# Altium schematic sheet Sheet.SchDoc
size A4
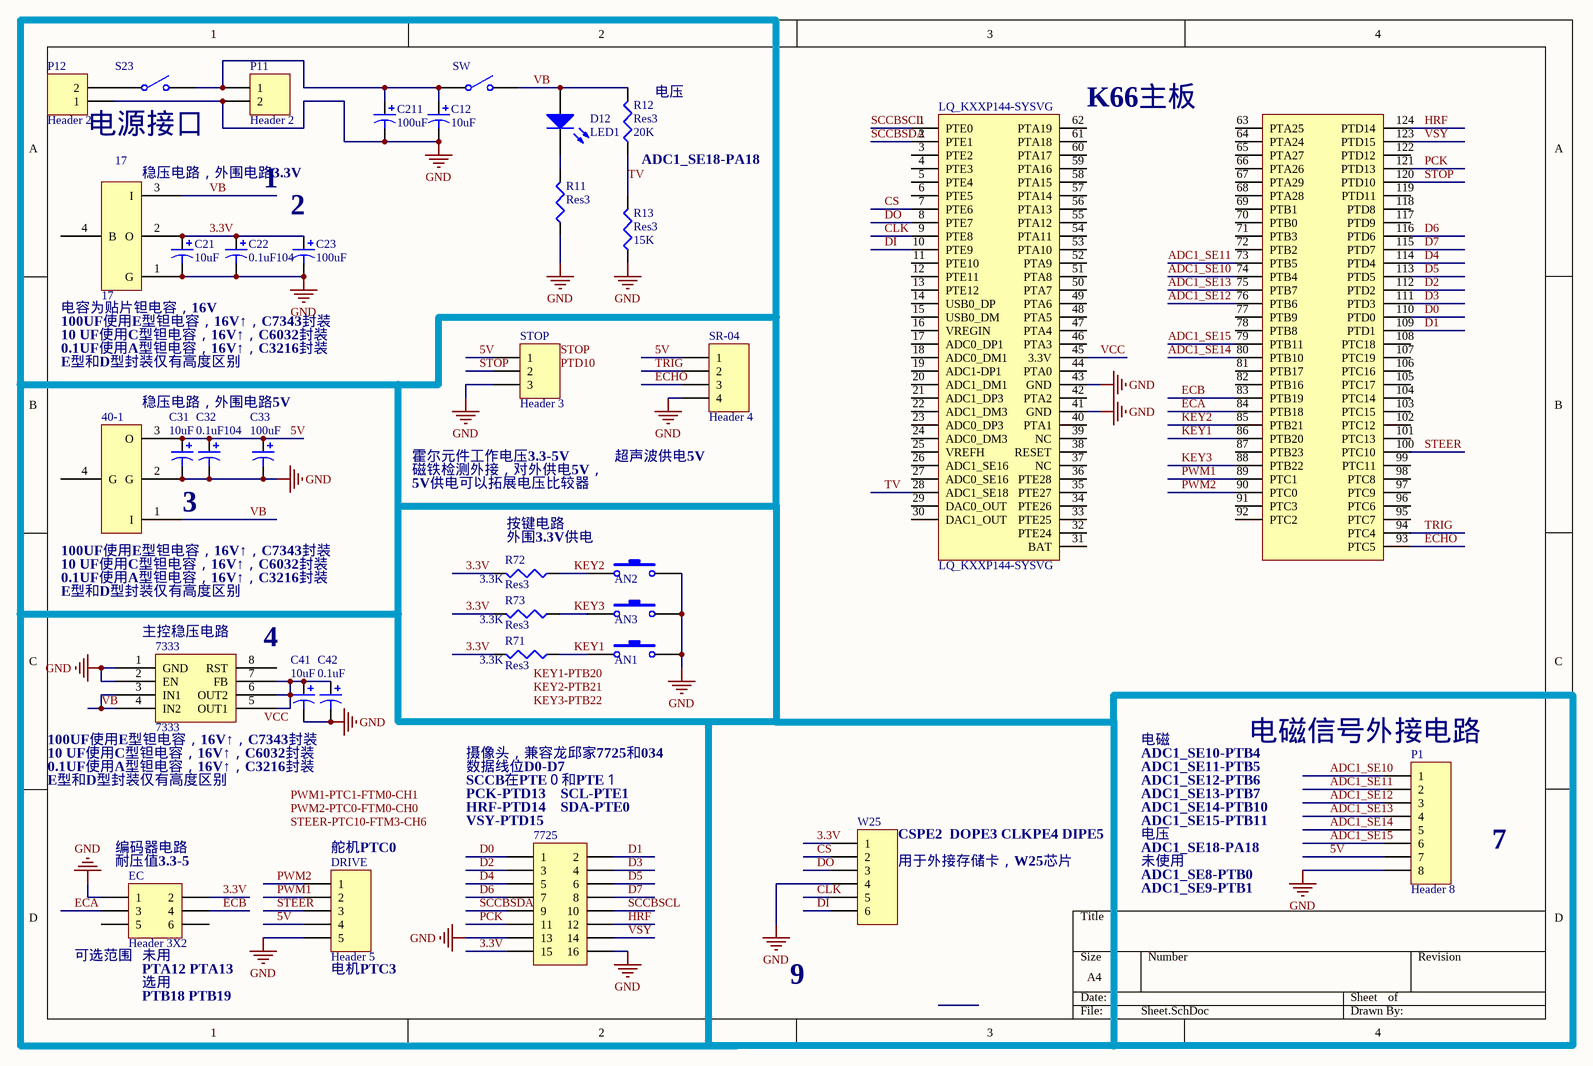
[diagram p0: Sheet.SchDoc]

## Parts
17  17  [SOT-223]
40-1  40-1  [TO-220B]  (value not drawn)
7333  7333  [SO8_N]
7725  Header 8X2  [HDR2X8]  (value not drawn)
AN1  Button  [SMT4*6*2.5]  (value not drawn)
AN2  Button  [SMT4*6*2.5]  (value not drawn)
AN3  Button  [SMT4*6*2.5]  (value not drawn)
C12  value 10uF  [C6032]  (hidden comment: Cap Pol3)
C21  value 10uF  [C6032]  (hidden comment: Cap Pol3)
C22  value 0.1uF104  [C3216]  (hidden comment: Cap Pol3)
C23  value 100uF  [C7343]  (hidden comment: Cap Pol3)
C31  value 10uF  [C6032]  (hidden comment: Cap Pol3)
C32  value 0.1uF104  [C3216]  (hidden comment: Cap Pol3)
C33  value 100uF  [C7343]  (hidden comment: Cap Pol3)
C41  value 10uF  [C6032]  (hidden comment: Cap Pol3)
C42  value 0.1uF  [C3216]  (hidden comment: Cap Pol3)
C211  value 100uF  [C7343]  (hidden comment: Cap Pol3)
D12  LED1  [SMA]
DRIVE  Header 5  [HDR1X5]
EC  Header 3X2  [HDR2X3]
LQ_KXXP144-SYSVG  LQ_KXXP144-SYSVG  [LQ_KXXP144-SYSVG]
P1  Header 8  [HDR1X8]
P11  Header 2  [T_Plug]
P12  Header 2  [2PIN-5.08A]
R11  Res3  [R0805]
R12  Res3  value 20K  [R0805]
R13  Res3  value 15K  [R0805]
R71  Res3  value 3.3K  [R0805]
R72  Res3  value 3.3K  [R0805]
R73  Res3  value 3.3K  [R0805]
S1  SW  [MTS-103]
S23  S2W  [MTS-103]  (value not drawn)
SR-04  Header 4  [HDR1X4]
STOP  Header 3  [HDR1X3]
W25  MHDR1X6  [HDR1X6]  (value not drawn)

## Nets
GND: 17.1(G) 40-1.2(G) 7333.1(GND) 7333.2(EN) 7725.13 7725.16 AN1.1 AN2.1 AN3.1 C12.2 C21.2 C22.2 C23.2 C31.2 C32.2 C33.2 C41.2 C42.2 C211.2 DRIVE.5 EC.1 LQ_KXXP144-SYSVG.41(GND) LQ_KXXP144-SYSVG.43(GND) P1.8 P11.2 P12.1 R11.1 R13.1 SR-04.4 STOP.3 W25.4
3.3V: 17.2(O) 7725.15 C21.1 C22.1 C23.1 EC.2 R71.2 R72.2 R73.2 W25.1
5V: 40-1.3(O) C31.1 C32.1 C33.1 DRIVE.4 P1.7 SR-04.1 STOP.1
ADC1_SE10: LQ_KXXP144-SYSVG.74(PTB4) P1.1
ADC1_SE11: LQ_KXXP144-SYSVG.73(PTB5) P1.2
ADC1_SE12: LQ_KXXP144-SYSVG.76(PTB6) P1.3
ADC1_SE13: LQ_KXXP144-SYSVG.75(PTB7) P1.4
ADC1_SE14: LQ_KXXP144-SYSVG.80(PTB10) P1.5
ADC1_SE15: LQ_KXXP144-SYSVG.79(PTB11) P1.6
CLK: LQ_KXXP144-SYSVG.9(PTE8) W25.5
CS: LQ_KXXP144-SYSVG.7(PTE6) W25.2
D0: 7725.1 LQ_KXXP144-SYSVG.110(PTD0)
D1: 7725.2 LQ_KXXP144-SYSVG.109(PTD1)
D2: 7725.3 LQ_KXXP144-SYSVG.112(PTD2)
D3: 7725.4 LQ_KXXP144-SYSVG.111(PTD3)
D4: 7725.5 LQ_KXXP144-SYSVG.114(PTD4)
D5: 7725.6 LQ_KXXP144-SYSVG.113(PTD5)
D6: 7725.7 LQ_KXXP144-SYSVG.116(PTD6)
D7: 7725.8 LQ_KXXP144-SYSVG.115(PTD7)
DI: LQ_KXXP144-SYSVG.10(PTE9) W25.6
DO: LQ_KXXP144-SYSVG.8(PTE7) W25.3
ECA: EC.3 LQ_KXXP144-SYSVG.84(PTB18)
ECB: EC.4 LQ_KXXP144-SYSVG.83(PTB19)
ECHO: LQ_KXXP144-SYSVG.93(PTC5) SR-04.3
HRF: 7725.12 LQ_KXXP144-SYSVG.124(PTD14)
KEY1: AN1.2 LQ_KXXP144-SYSVG.86(PTB20) R71.1
KEY2: AN2.2 LQ_KXXP144-SYSVG.85(PTB21) R72.1
KEY3: AN3.2 LQ_KXXP144-SYSVG.88(PTB22) R73.1
PCK: 7725.11 LQ_KXXP144-SYSVG.121(PTD13)
PWM1: DRIVE.2 LQ_KXXP144-SYSVG.89(PTC1)
PWM2: DRIVE.1 LQ_KXXP144-SYSVG.90(PTC0)
SCCBSCL: 7725.10 LQ_KXXP144-SYSVG.1(PTE0)
SCCBSDA: 7725.9 LQ_KXXP144-SYSVG.2(PTE1)
STEER: DRIVE.3 LQ_KXXP144-SYSVG.100(PTC10)
STOP: LQ_KXXP144-SYSVG.120(PTD10) STOP.2
TRIG: LQ_KXXP144-SYSVG.94(PTC4) SR-04.2
TV: LQ_KXXP144-SYSVG.28(ADC1_SE18) R12.1 R13.2
VB: 17.3(I) 40-1.1(I) 7333.3(IN1) 7333.4(IN2) D12.1(A) R12.2 S1.2(NO)
VCC: 7333.5(OUT1) 7333.6(OUT2) 7333.7(FB) C41.1 C42.1 LQ_KXXP144-SYSVG.45(3.3V)
VSY: 7725.14 LQ_KXXP144-SYSVG.123(PTD15)
NetC12_1: C12.1 C211.1 P11.1 S1.1(COMMON) S23.2(NO)
NetD12_2: D12.2(K) R11.2
NetP12_2: P12.2 S23.1(COMMON)

Not connected (* = marked no-connect by the designer): 17 4(B); 40-1 4(G); 7333 8(RST); EC 5 6; LQ_KXXP144-SYSVG 3(PTE2) 4(PTE3) 5(PTE4) 6(PTE5) 11(PTE10) 12(PTE11) 13(PTE12) 14(USB0_DP) 15(USB0_DM) 16(VREGIN) 17(ADC0_DP1) 18(ADC0_DM1) 19(ADC1-DP1) 20(ADC1_DM1) 21(ADC1_DP3) 22(ADC1_DM3) 23(ADC0_DP3) 24(ADC0_DM3) 25(VREFH) 26(ADC1_SE16) 27(ADC0_SE16) 29(DAC0_OUT) 30(DAC1_OUT) 31(BAT) 32(PTE24) 33(PTE25) 34(PTE26) 35(PTE27) 36(PTE28) 37(NC) 38(RESET) 39(NC) 40(PTA1) 42(PTA2) 44(PTA0) 46(PTA3) 47(PTA4) 48(PTA5) 49(PTA6) 50(PTA7) 51(PTA8) 52(PTA9) 53(PTA10) 54(PTA11) 55(PTA12) 56(PTA13) 57(PTA14) 58(PTA15) 59(PTA16) 60(PTA17) 61(PTA18) 62(PTA19) 63(PTA25) 64(PTA24) 65(PTA27) 66(PTA26) 67(PTA29) 68(PTA28) 69(PTB1) 70(PTB0) 71(PTB3) 72(PTB2) 77(PTB9) 78(PTB8) 81(PTB17) 82(PTB16) 87(PTB23) 91(PTC3) 92(PTC2) 95(PTC7) 96(PTC6) 97(PTC9) 98(PTC8) 99(PTC11) 101(PTC13) 102(PTC12) 103(PTC15) 104(PTC14) 105(PTC17) 106(PTC16) 107(PTC19) 108(PTC18) 117(PTD9) 118(PTD8) 119(PTD11) 122(PTD12)

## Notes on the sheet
- (near R12) 电压
- (near LQ_KXXP144-SYSVG) K66主板
- (near P12) 电源接口
- (near 17) 稳压电路，外围电路3.3V
- 1
- (near R12) ADC1_SE18-PA18
- (near C23) 2
- (near 17) 电容为贴片钽电容，16V
- 100UF使用E型钽电容，16V↑，C7343封装
- 10 UF使用C型钽电容，16V↑，C6032封装
- 0.1UF使用A型钽电容，16V↑，C3216封装
- E型和D型封装仅有高度区别
- 稳压电路，外围电路5V
- 霍尔元件工作电压3.3-5V
- 超声波供电5V
- 3
- 磁铁检测外接，对外供电5V，
- 5V供电可以拓展电压比较器
- (near R72) 按键电路
- (near 40-1) 100UF使用E型钽电容，16V↑，C7343封装
- (near 40-1) 10 UF使用C型钽电容，16V↑，C6032封装
- (near R72) 外围3.3V供电
- (near 7333) 主控稳压电路
- 4
- (near 7333) 100UF使用E型钽电容，16V↑，C7343封装
- (near 7333) 10 UF使用C型钽电容，16V↑，C6032封装
- (near 7333) 0.1UF使用A型钽电容，16V↑，C3216封装
- 摄像头，兼容龙邱家7725和034
- 数据线位D0-D7
- SCCB在PTE０和PTE１
- PCK-PTD13
- SCL-PTE1
- ADC1_SE10-PTB4
- ADC1_SE11-PTB5
- ADC1_SE12-PTB6
- ADC1_SE13-PTB7
- 电磁
- (near P1) 电磁信号外接电路
- (near EC) 编码器电路
- (near EC) 耐压值3.3-5
- (near DRIVE) 舵机PTC0
- (near 7725) HRF-PTD14
- (near 7725) VSY-PTD15
- (near 7725) SDA-PTE0
- (near W25) 用于外接存储卡，W25芯片
- (near W25) CSPE2  DOPE3 CLKPE4 DIPE5
- ADC1_SE14-PTB10
- ADC1_SE15-PTB11
- 未使用
- ADC1_SE18-PA18
- 电压
- 7
- ADC1_SE8-PTB0
- ADC1_SE9-PTB1
- (near EC) 可选范围
- (near EC) PTA12 PTA13
- PTB18 PTB19
- (near EC) 选用
- (near EC) 未用
- (near DRIVE) 电机PTC3
- 9
- Labels drawn without touching a wire or pin: KEY1-PTB20, KEY2-PTB21, KEY3-PTB22, PTD10, PWM1-PTC1-FTM0-CH1, PWM2-PTC0-FTM0-CH0, STEER-PTC10-FTM3-CH6, STOP

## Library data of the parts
17 = AMS1117: SOT-223
40-1 = LM2940: SOT-223
7725 = Header 8X2: Header, 8-Pin, Dual row
C12 C21-C23 C31-C33 C41 C42 C211 = Cap Pol3: Polarized Capacitor (Surface Mount)
D12 = LED3: Typical BLUE SiC LED
DRIVE = Header 5: Header, 5-Pin
EC = Header 3X2: Header, 3-Pin, Dual row
P1 = Header 8: Header, 8-Pin
P11 P12 = Header 2: Header, 2-Pin
R11-R13 R71-R73 = Res3: Resistor
S1 S23 = SW-SPST: Single-Pole, Single-Throw Switch
SR-04 = Header 4: Header, 4-Pin
STOP = Header 3: Header, 3-Pin
W25 = MHDR1X6: Header, 6-Pin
